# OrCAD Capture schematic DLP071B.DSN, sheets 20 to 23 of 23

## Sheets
20 PAGE04 - TEST INTERFACE CONNECT: size A3
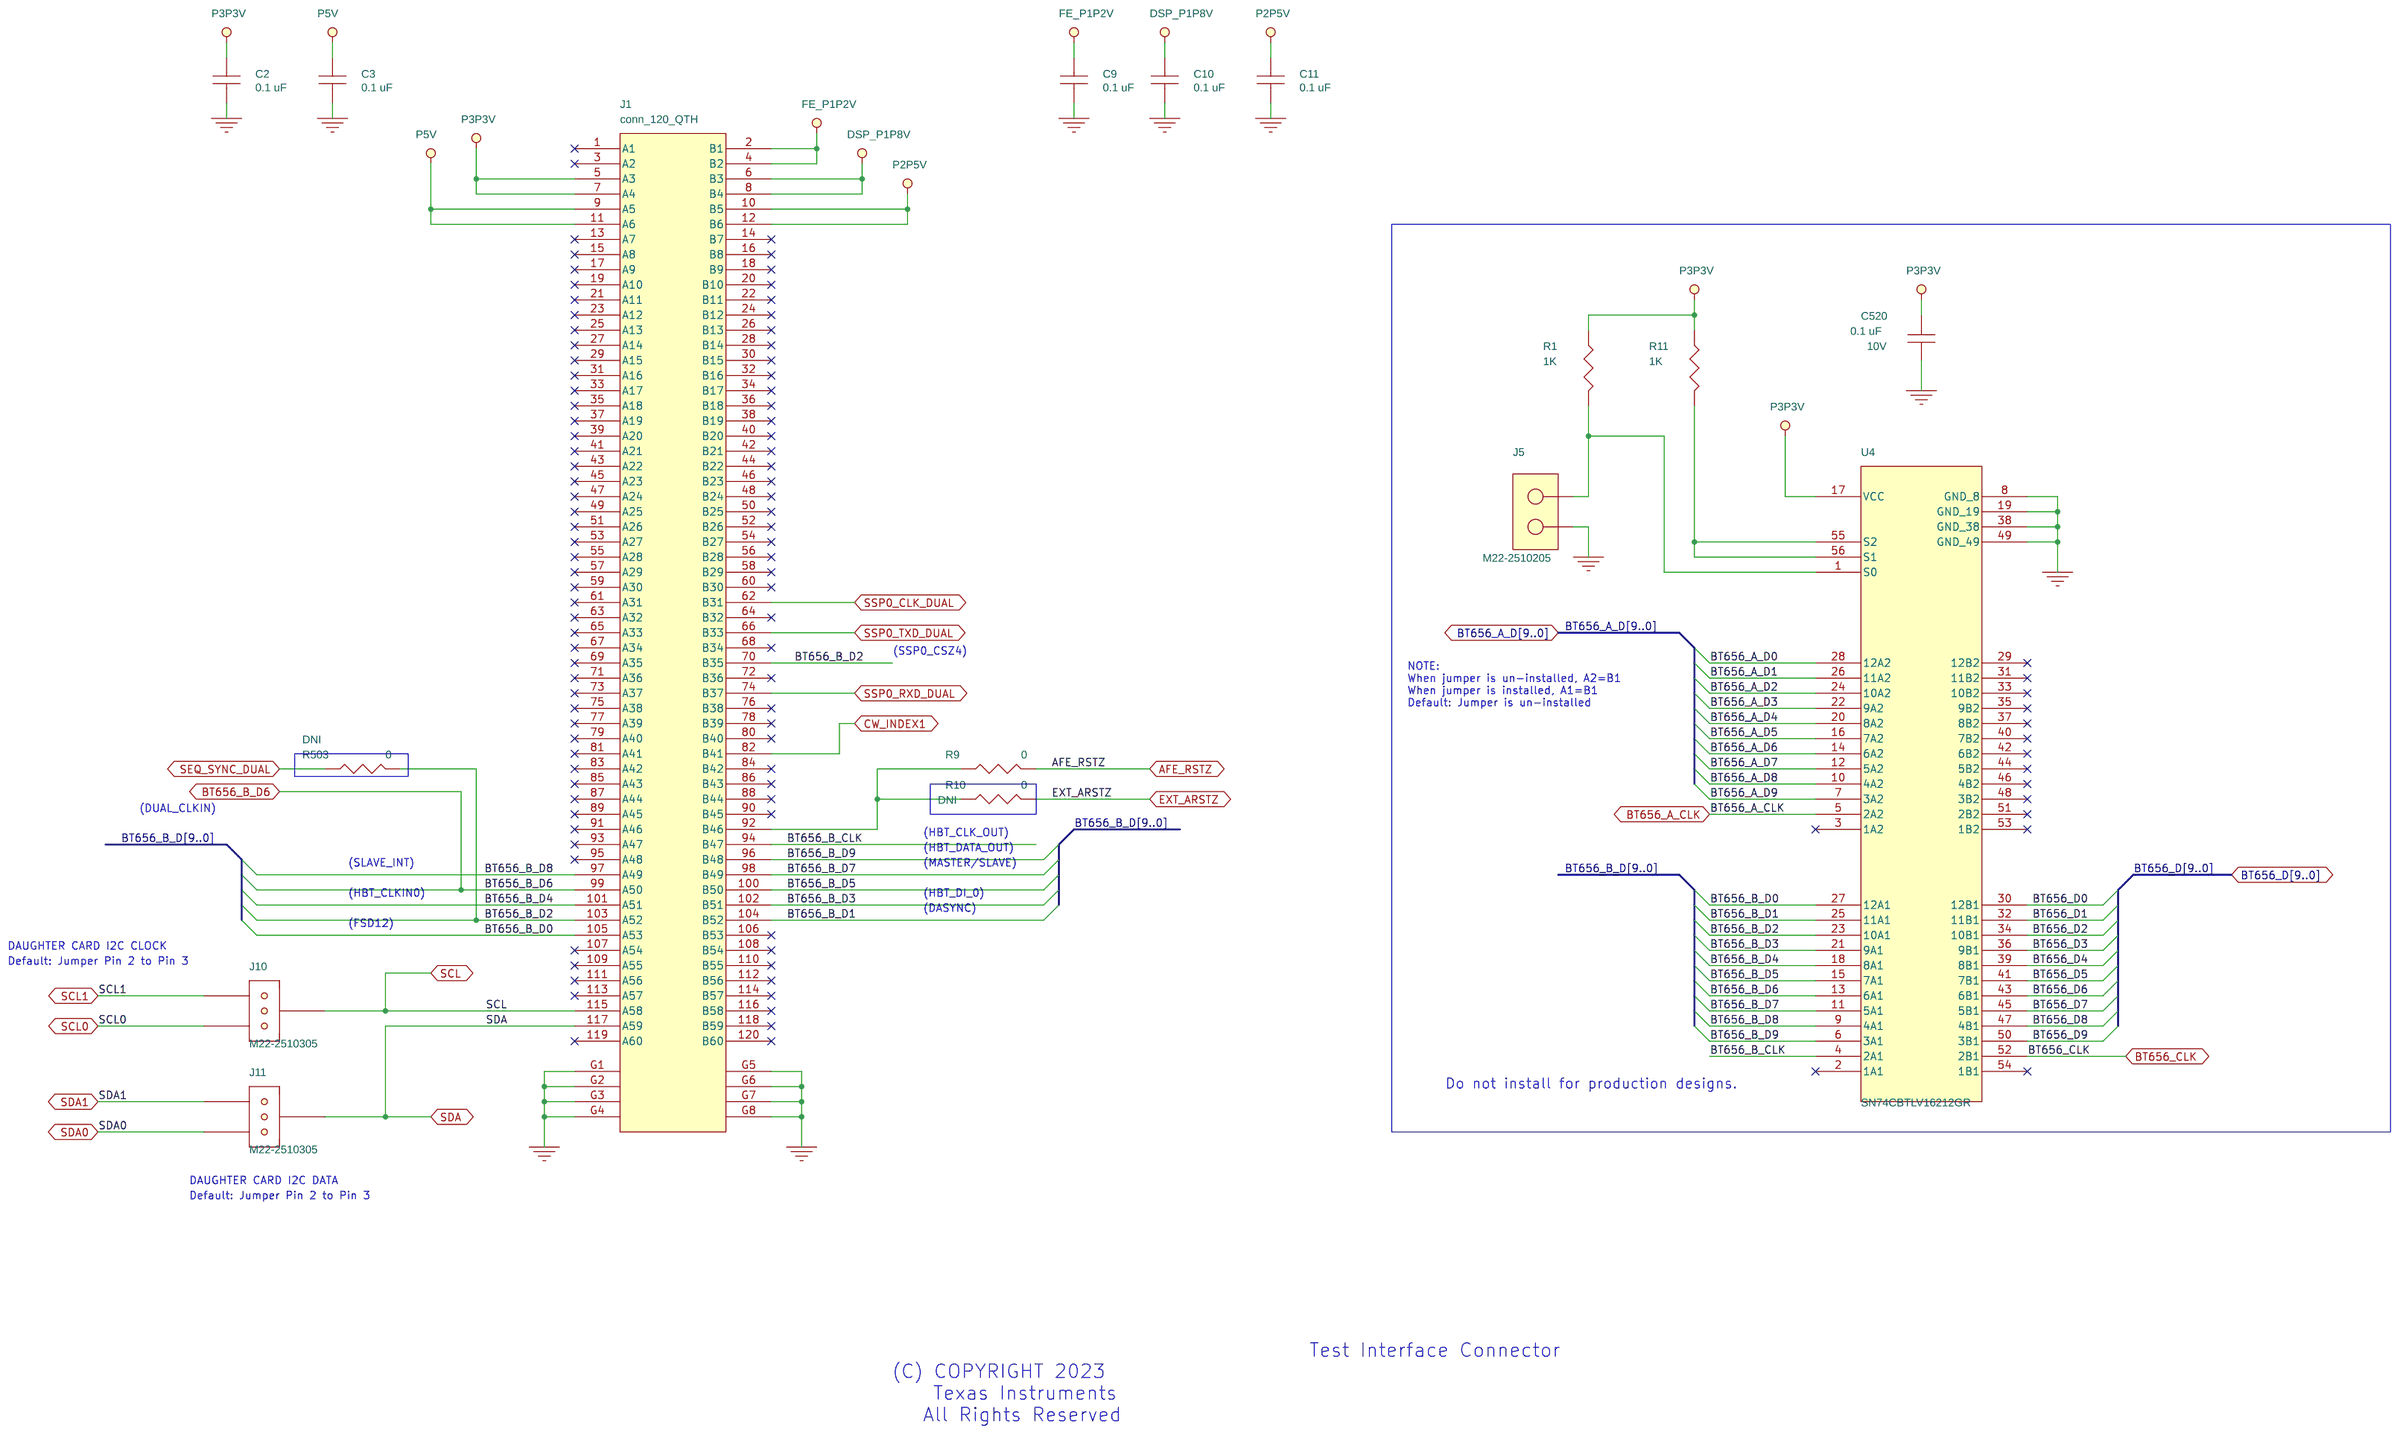
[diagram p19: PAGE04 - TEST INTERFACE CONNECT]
21 PAGE03 - AFE1000 INTERFACE: size A3
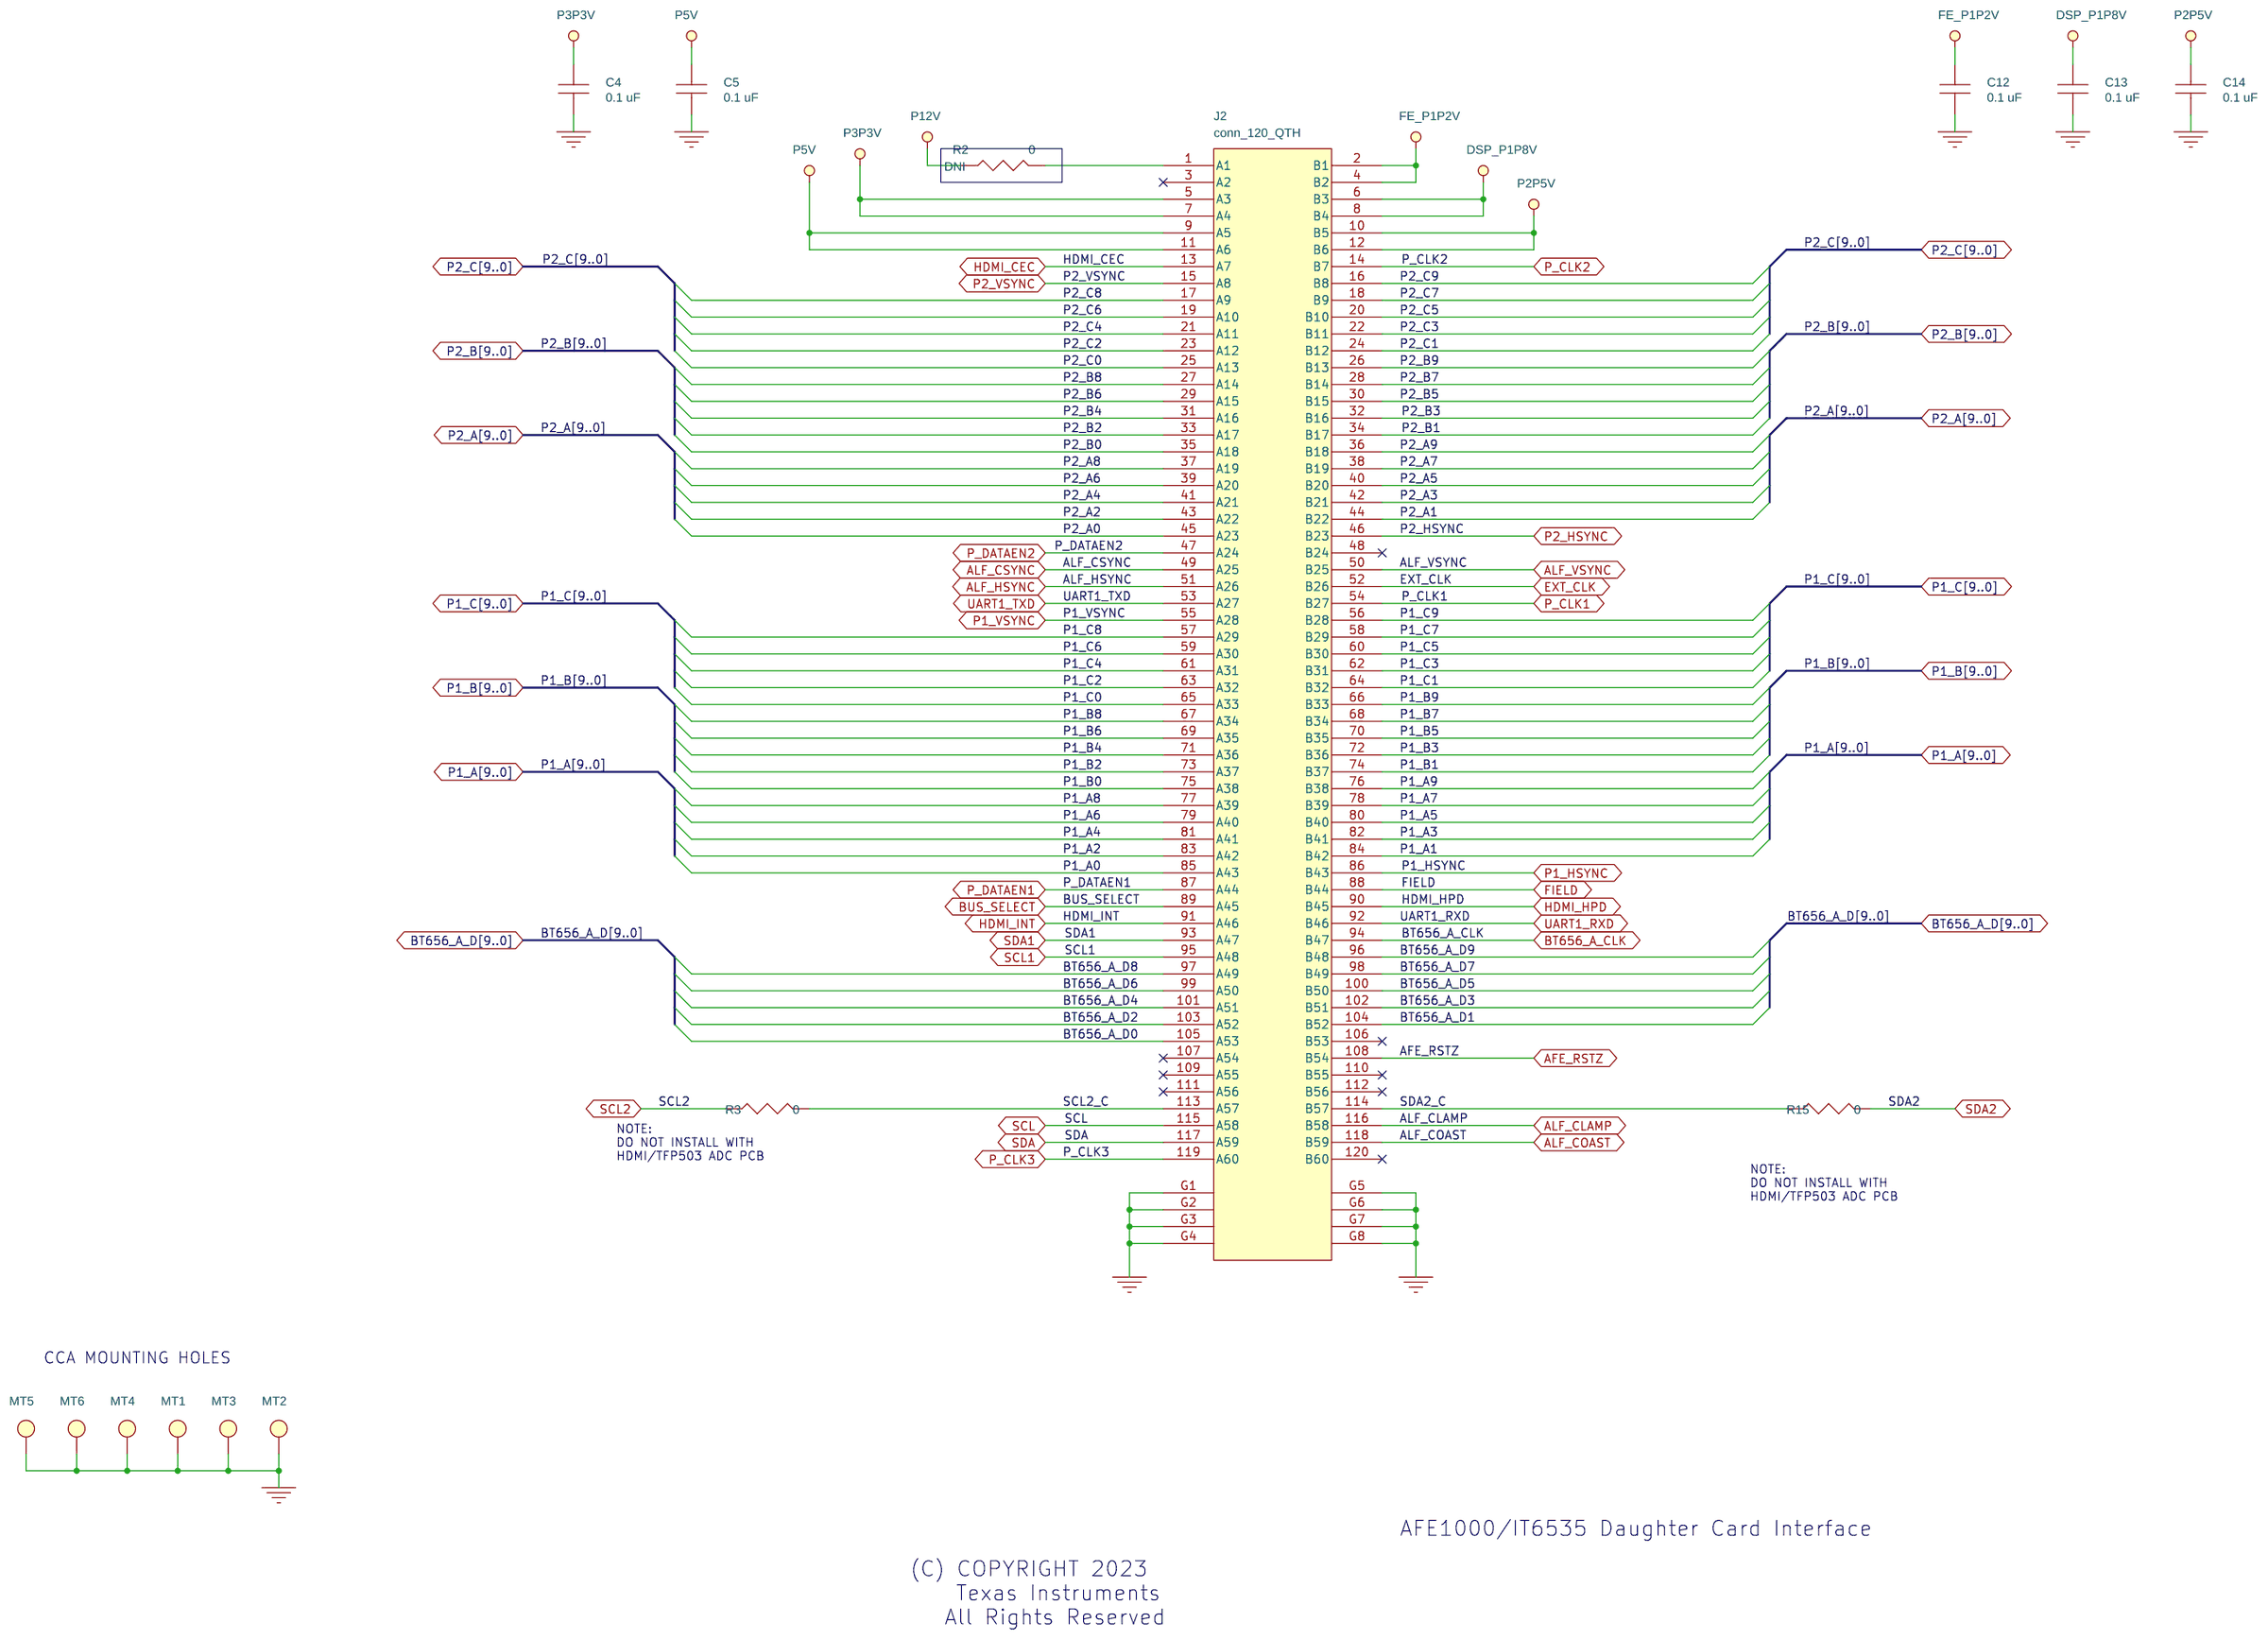
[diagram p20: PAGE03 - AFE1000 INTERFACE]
22 PAGE02 - BLOCK DIAGRAM
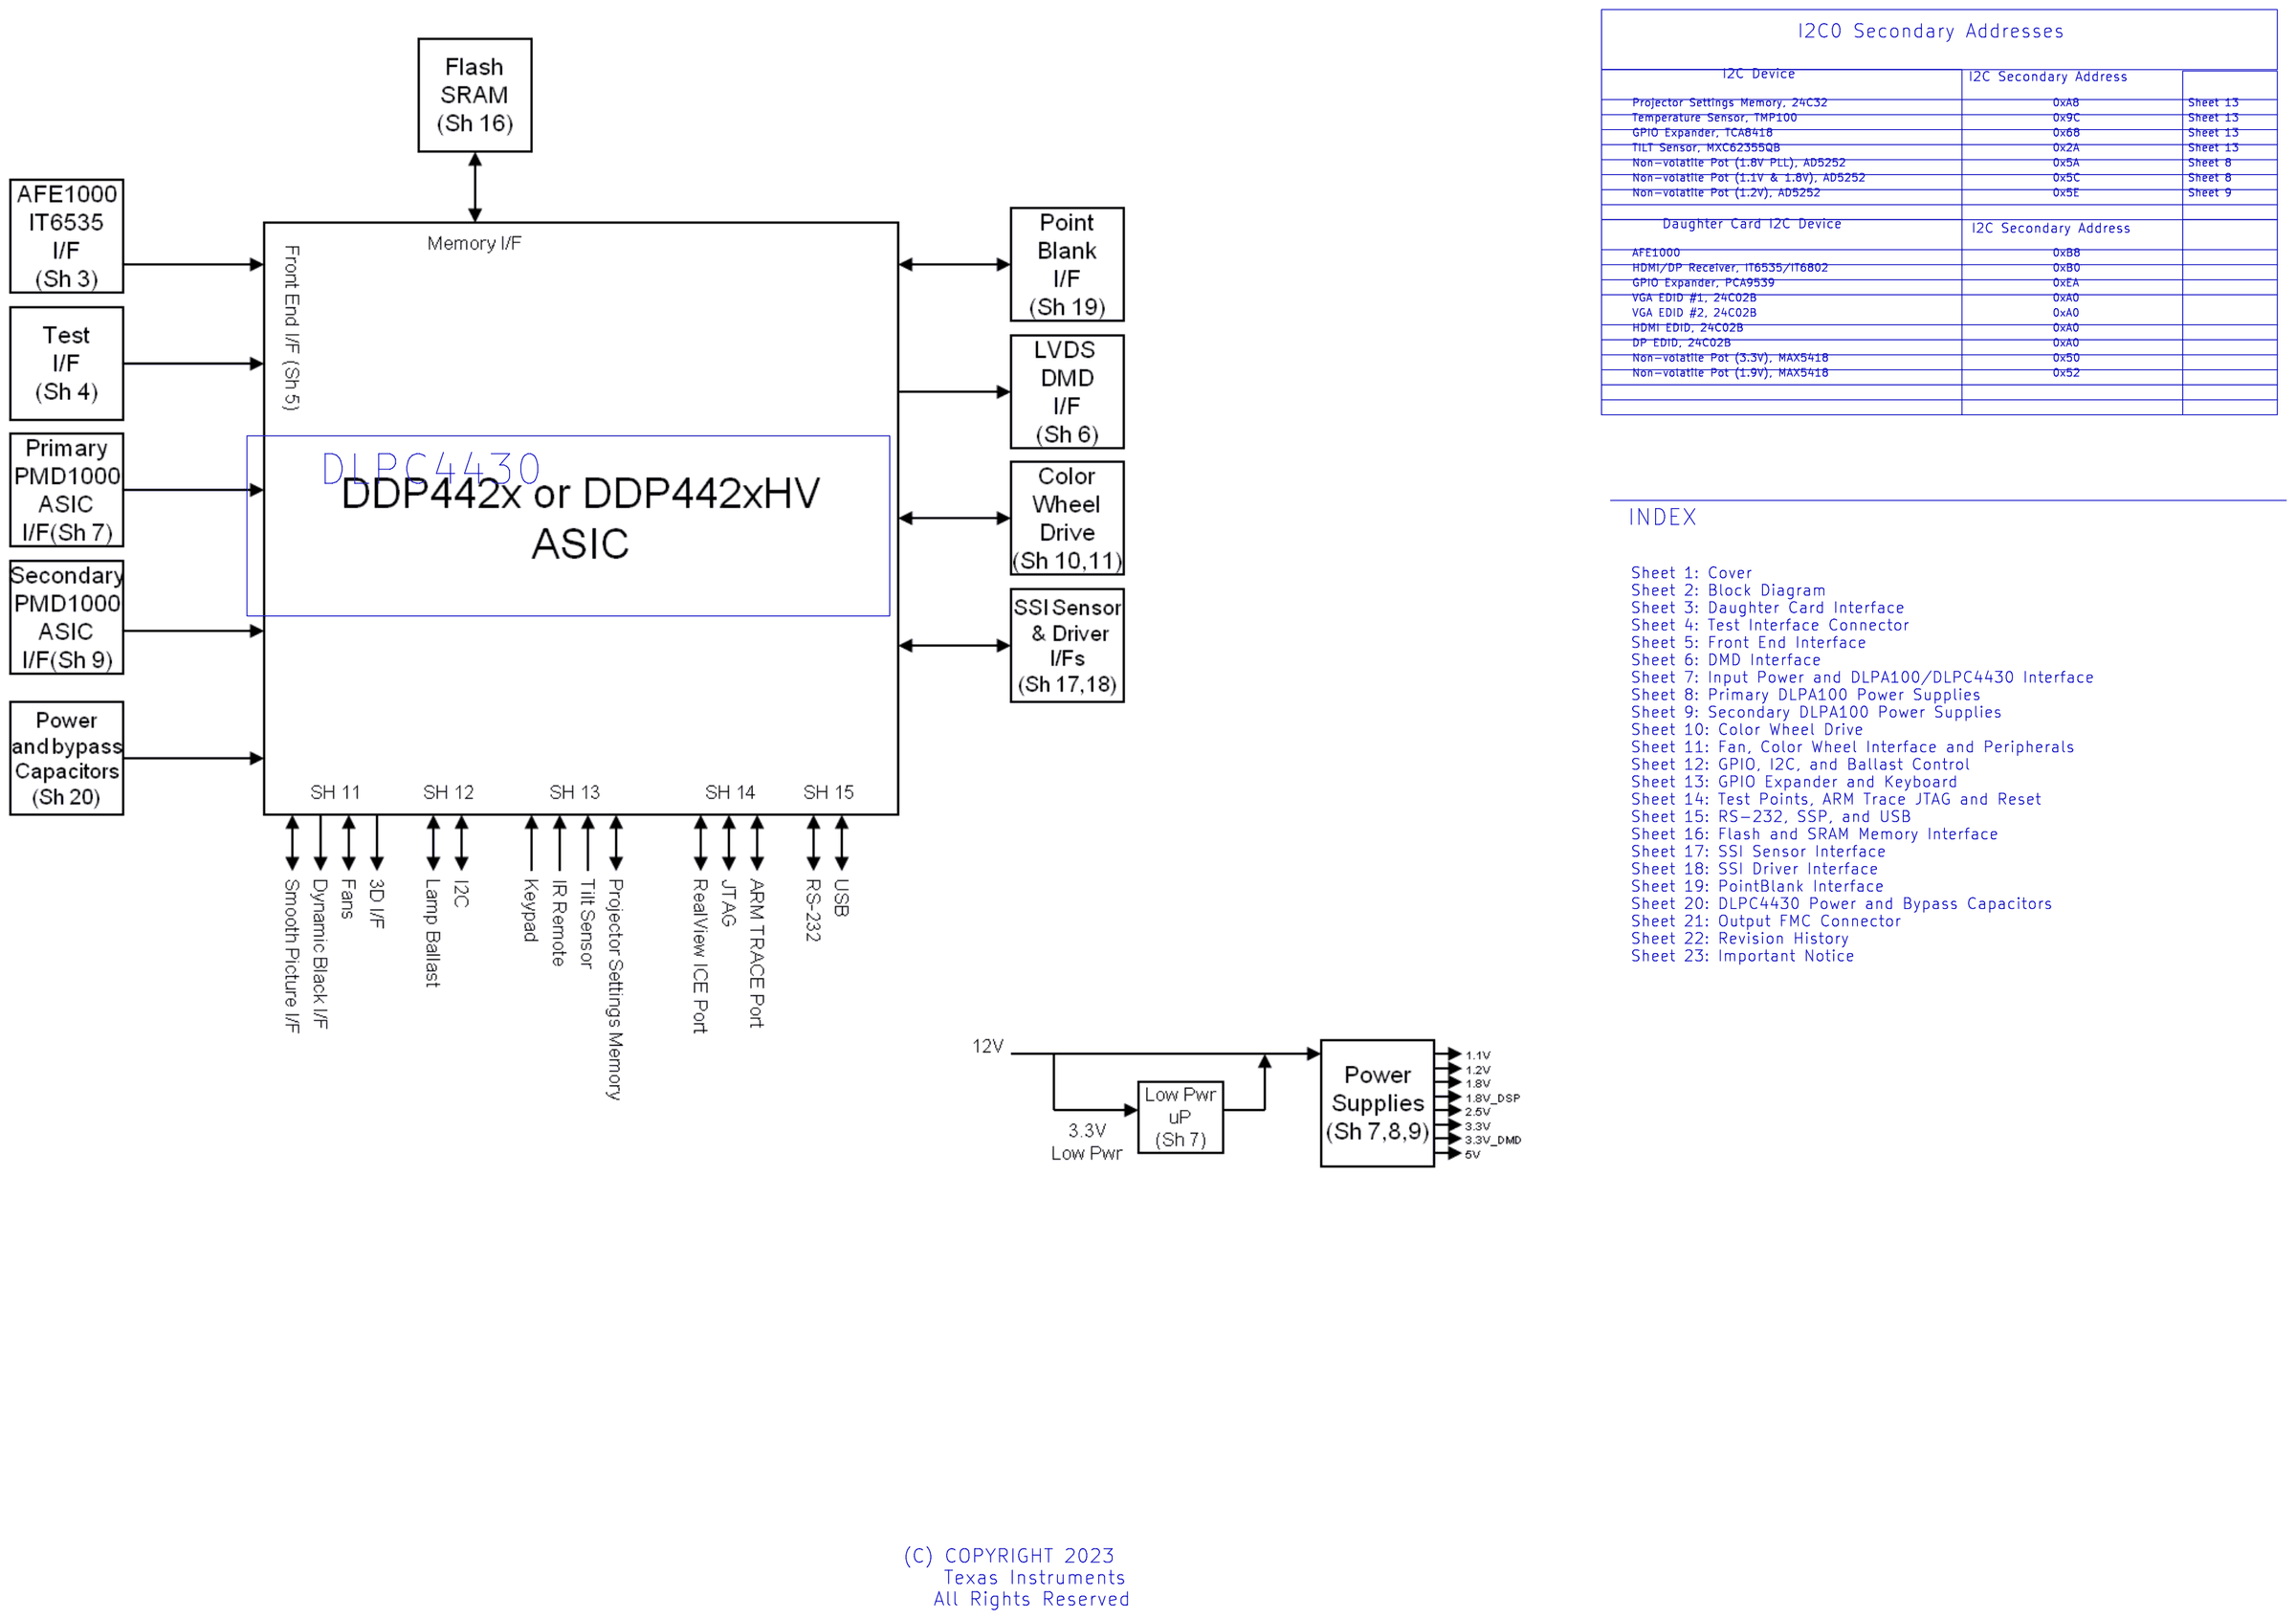
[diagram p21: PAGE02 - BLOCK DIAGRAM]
23 PAGE01 - TITLE: rev: D
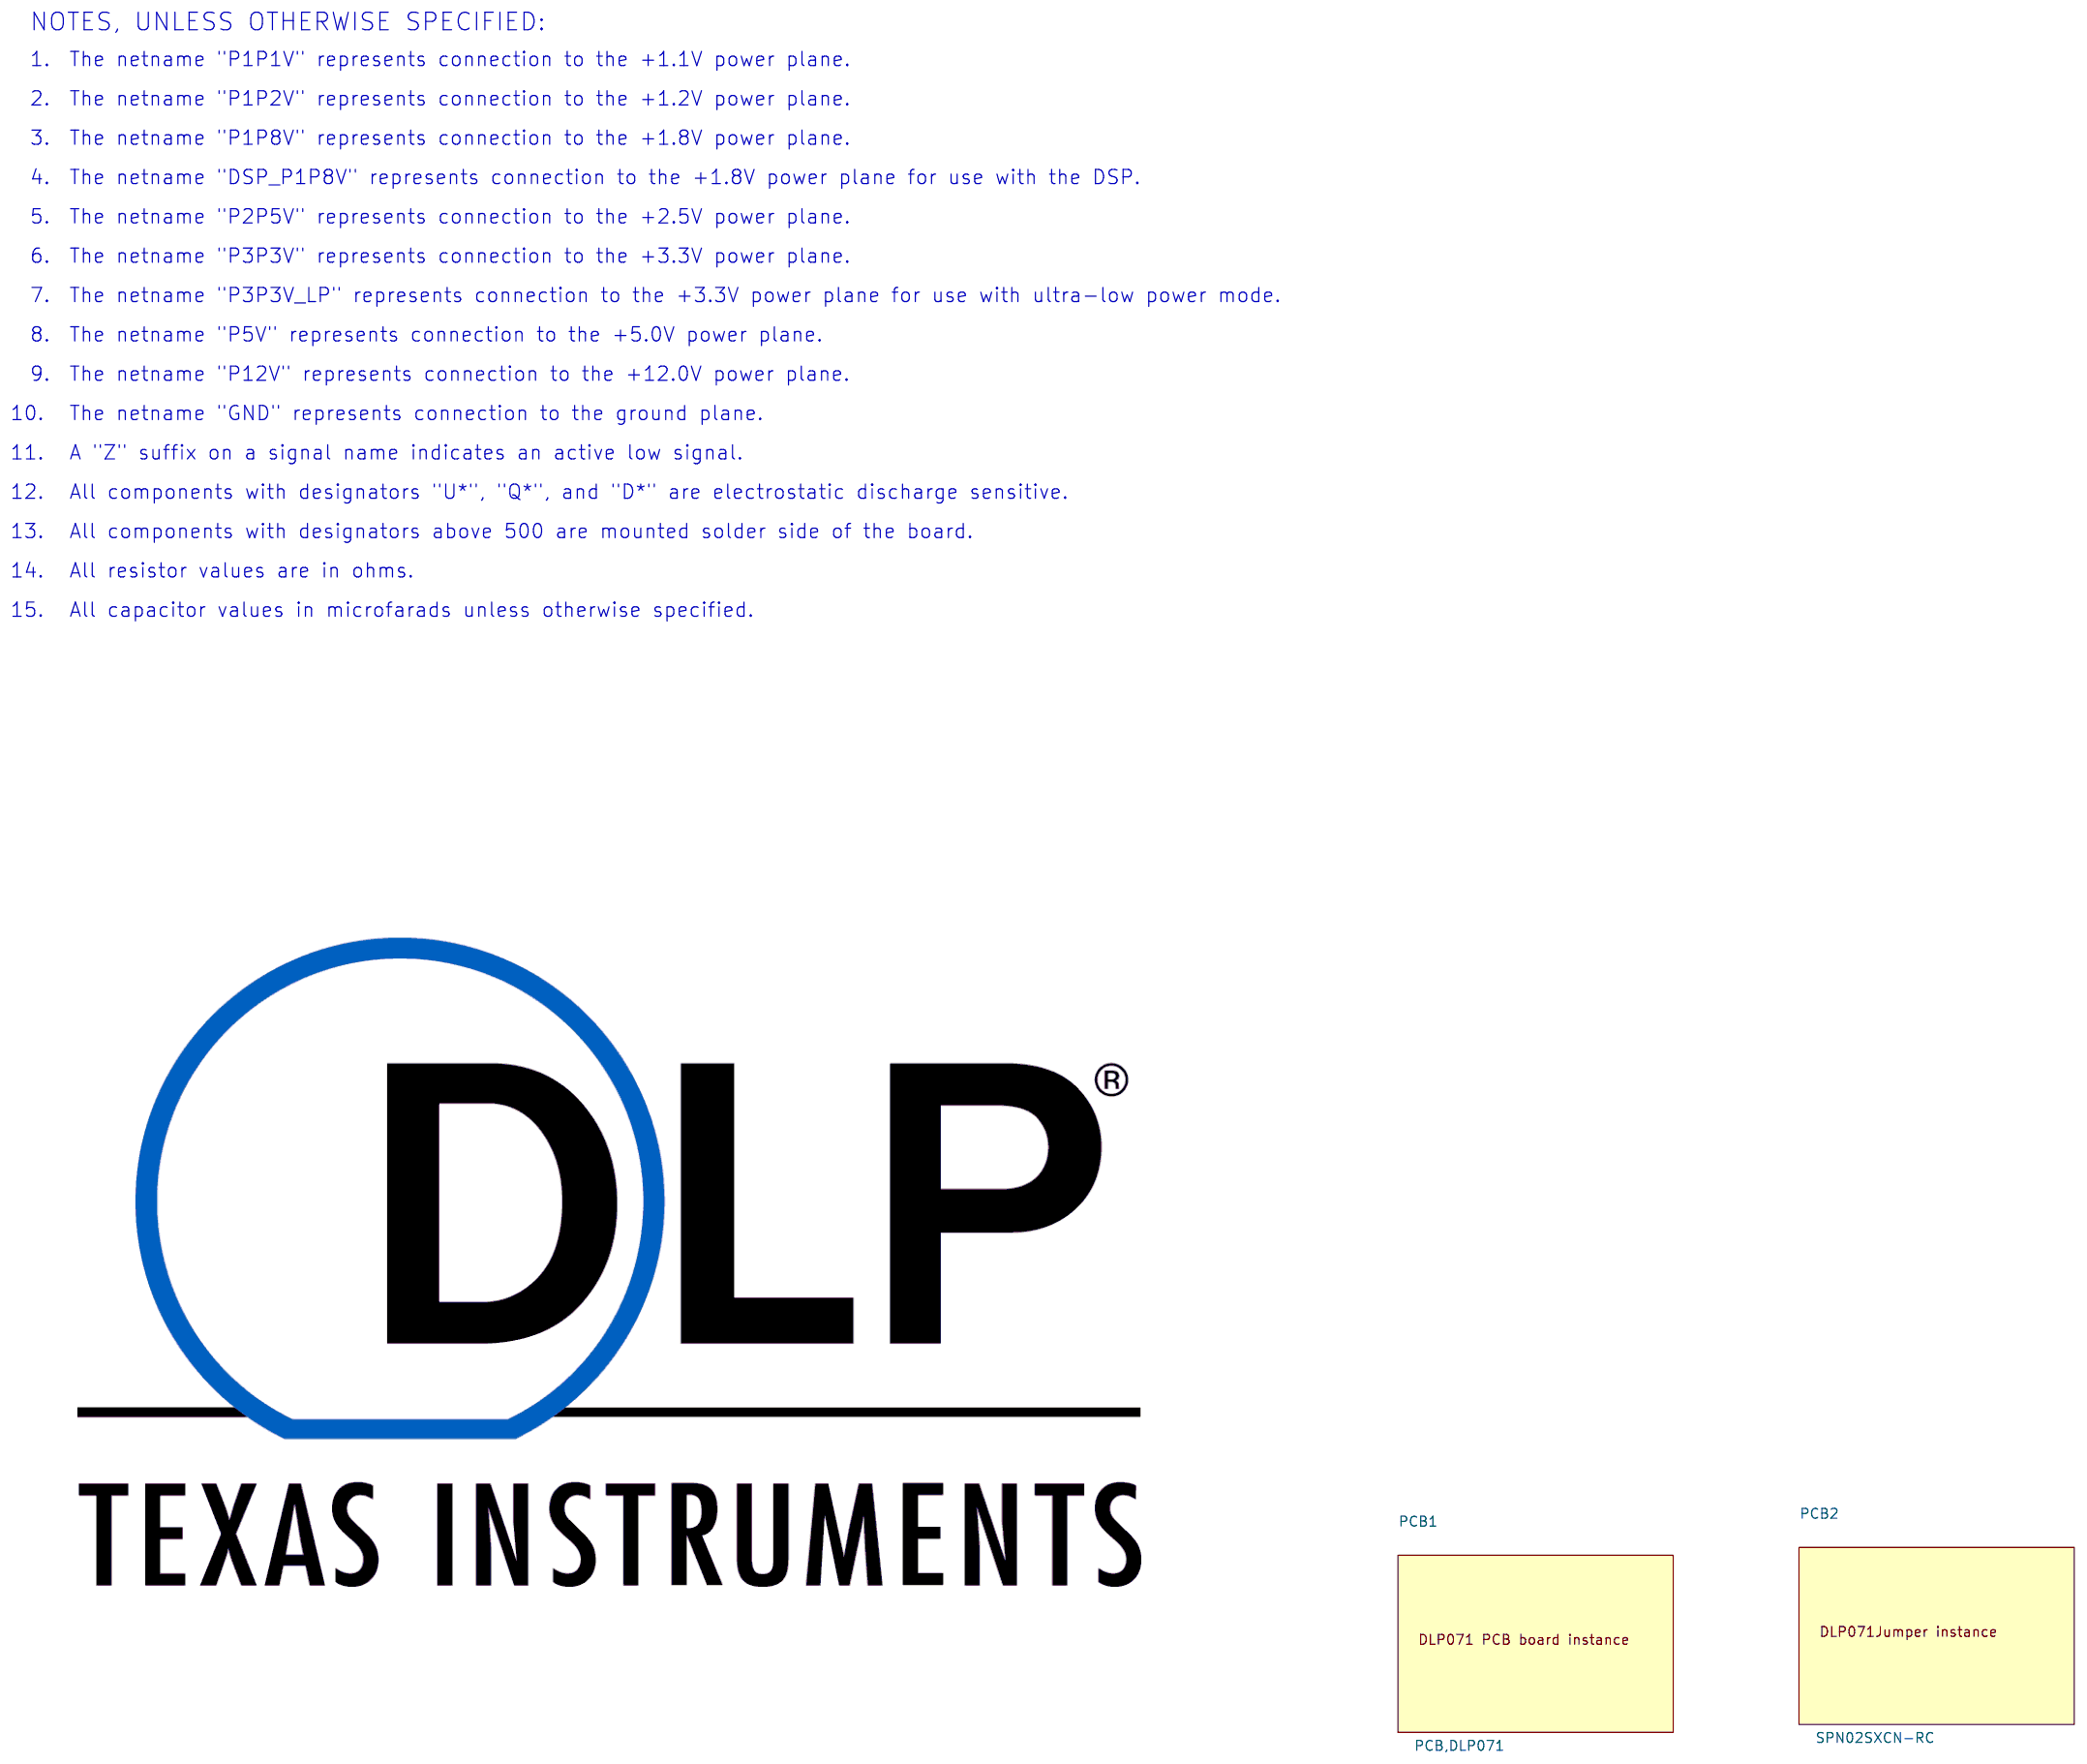
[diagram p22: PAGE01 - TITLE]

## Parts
sheet PAGE01 - TITLE
PCB1  PCB,DLP071
PCB2  SPN02SXCN-RC
sheet PAGE03 - AFE1000 INTERFACE
C4  0.1 uF  [CAP_0402]
C5  0.1 uF  [CAP_0402]
C12  0.1 uF  [CAP_0402]
C13  0.1 uF  [CAP_0402]
C14  0.1 uF  [CAP_0402]
J2  conn_120_QTH  [CN120_QTH_SAMTEC]
MT1  MOUNTING HOLE  [MH276-157GND-a]
MT2  MOUNTING HOLE  [MH276-157GND-a]
MT3  MOUNTING HOLE  [MH276-157GND-a]
MT4  MOUNTING HOLE  [MH276-157GND-a]
MT5  MOUNTING HOLE  [MH276-157GND-a]
MT6  MOUNTING HOLE  [MH276-157GND-a]
R2  0  [RES_0402]
R3  0  [RES_0402]
R15  0  [RES_0402]
sheet PAGE04 - TEST INTERFACE CONNECT
C2  0.1 uF  [CAP_0402]
C3  0.1 uF  [CAP_0402]
C9  0.1 uF  [CAP_0402]
C10  0.1 uF  [CAP_0402]
C11  0.1 uF  [CAP_0402]
C520  0.1 uF  [CAP_0402]
J1  conn_120_QTH  [CN120_QTH_SAMTEC]
J5  HDR_2  [HDR2_2MM]
J10  JUMPER-1x3  [HDR1X3-TMM1030X-X-S_SAM]
J11  JUMPER-1x3  [HDR1X3-TMM1030X-X-S_SAM]
R1  1K  [RES_0402]
R9  0  [RES_0402]
R10  0  [RES_0402]
R11  1K  [RES_0402]
R503  0  [RES_0402]
U4  74CBTLV16212  [SOIC56-DGG_TI]

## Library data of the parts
PCB1 = DLP027_0: DNI: DNI
PCB2 = DLP027_1: CONN JUMPER SHORTING 2MM GOLD; MFG: Sullins Conn.
C2-C5 C9-C14 C520 = CAP_NP: Capacitor; MFG: KEMET; Part Number: C0402C104K8RACTU; RATING: 10V; SOURCE: DIGI 399-3520-1-ND; TOLERANCE: 10%; Type: X7R
J1 J2 = conn_120_QTH: Connector, 120 pin; MFG: SAMTEC; Part Number: QTH-060-01-L-D-A; SOURCE: SAMTEC
MT1-MT6 = Testpoint_0: Mounting Hole; MFG: NA; Part Number: NA; SOURCE: NA
R2 R10 R503 = R: Resistor; DNI: DNI; ICA_MFR_NAME: PANASONIC; ICA_PARTNUM: $$1785048$$ERJ-3GSYJ102; MFG: PANASONIC; Part Number: ERJ-2GE0R00X; RATING: 1/10W; SOURCE: DIGI P0.0JCT-ND
R3 R9 R15 = R: Resistor; ICA_MFR_NAME: PANASONIC; ICA_PARTNUM: $$1785048$$ERJ-3GSYJ102; MFG: PANASONIC; Part Number: ERJ-2GE0R00X; RATING: 1/10W; SOURCE: DIGI P0.0JCT-ND
J5 = HDR_2: Jumper, 1x2; MFG: HARWIN; Part Number: M22-2510205; SOURCE: DIGI 952-1311-ND
J10 J11 = JUMPER-1x3: Jumper, 1x3; MFG: HARWIN; Part Number: M22-2510305; SOURCE: DIGI 952-1312-ND
R1 R11 = R: Resistor; ICA_MFR_NAME: PANASONIC; ICA_PARTNUM: $$1785048$$ERJ-3GSYJ102; MFG: PANASONIC; Part Number: ERJ-2GEJ102X; RATING: 1/10W; SOURCE: DIGI P1.0KJCT-ND; TOLERANCE: 5%
U4 = SN74CBTLV16212: IC, Bus-Exchange Switch; MFG: TI; Part Number: SN74CBTLV16212GR; SOURCE: DIGI 296-9102-1-ND

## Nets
GND: C2.2 C3.2 C4.2 C5.2 C9.2 C10.2 C11.2 C12.2 C13.2 C14.2 C520.1 J1.G1 J1.G2 J1.G3 J1.G4 J1.G5 J1.G6 J1.G7 J1.G8 J2.G1 J2.G2 J2.G3 J2.G4 J2.G5 J2.G6 J2.G7 J2.G8 J5.2 MT1.1 MT2.1 MT3.1 MT4.1 MT5.1 MT6.1 U4.8(GND) U4.19(GND) U4.38(GND) U4.49(GND) ; also on sheet 1 4 5 6 7 8 9 10 11 12 13 14 15 16 17 18
P5V: C3.1 C5.1 J1.9(A5) J1.11(A6) J2.9(A5) J2.11(A6) ; also on sheet 5 7 12 13 16
P12V: R2.1 ; also on sheet 1 6 13 14 15 16 17
AFE_RSTZ: J2.108(B54) R9.1 ; also on sheet 19
ALF_CLAMP: J2.116(B58) ; also on sheet 12
ALF_COAST: J2.118(B59) ; also on sheet 12
ALF_CSYNC: J2.49(A25) ; also on sheet 19
ALF_HSYNC: J2.51(A26) ; also on sheet 19
ALF_VSYNC: J2.50(B25) ; also on sheet 19
BT656_A_CLK: J2.94(B47) U4.5(2A2)
BT656_A_D0: J2.105(A53) U4.28(12A2)
BT656_A_D1: J2.104(B52) U4.26(11A2)
BT656_A_D2: J2.103(A52) U4.24(10A2)
BT656_A_D3: J2.102(B51) U4.22(9A2)
BT656_A_D4: J2.101(A51) U4.20(8A2)
BT656_A_D5: J2.100(B50) U4.16(7A2)
BT656_A_D6: J2.99(A50) U4.14(6A2)
BT656_A_D7: J2.98(B49) U4.12(5A2)
BT656_A_D8: J2.97(A49) U4.10(4A2)
BT656_A_D9: J2.96(B48) U4.7(3A2)
BT656_B_CLK: J1.94(B47) U4.4(2A1)
BT656_B_D0: J1.105(A53) U4.27(12A1)
BT656_B_D1: J1.104(B52) U4.25(11A1)
BT656_B_D2: J1.70(B35) J1.103(A52) R503.1 U4.23(10A1)
BT656_B_D3: J1.102(B51) U4.21(9A1)
BT656_B_D4: J1.101(A51) U4.18(8A1)
BT656_B_D5: J1.100(B50) U4.15(7A1)
BT656_B_D6: J1.99(A50) U4.13(6A1) ; also on sheet 17
BT656_B_D7: J1.98(B49) U4.11(5A1)
BT656_B_D8: J1.97(A49) U4.9(4A1)
BT656_B_D9: J1.96(B48) U4.6(3A1)
BT656_CLK: U4.52(2B1) ; also on sheet 12
BT656_D0: U4.30(12B1) ; also on sheet 12
BT656_D1: U4.32(11B1) ; also on sheet 12
BT656_D2: U4.34(10B1) ; also on sheet 12
BT656_D3: U4.36(9B1) ; also on sheet 12
BT656_D4: U4.39(8B1) ; also on sheet 12
BT656_D5: U4.41(7B1) ; also on sheet 12
BT656_D6: U4.43(6B1) ; also on sheet 12
BT656_D7: U4.45(5B1) ; also on sheet 12
BT656_D8: U4.47(4B1) ; also on sheet 12
BT656_D9: U4.50(3B1) ; also on sheet 12
BUS_SELECT: J2.89(A45) ; also on sheet 11
CW_INDEX1: J1.82(B41) ; also on sheet 13 17
DSP_P1P8V: C10.1 C13.1 J1.6(B3) J1.8(B4) J2.6(B3) J2.8(B4) ; also on sheet 15
EXT_ARSTZ: R10.1 ; also on sheet 1 13 17
EXT_CLK: J2.52(B26) ; also on sheet 19
FE_P1P2V: C9.1 C12.1 J1.2(B1) J1.4(B2) J2.2(B1) J2.4(B2) ; also on sheet 15
FIELD: J2.88(B44) ; also on sheet 12 19
HDMI_CEC: J2.13(A7) ; also on sheet 19
HDMI_HPD: J2.90(B45) ; also on sheet 11
HDMI_INT: J2.91(A46) ; also on sheet 19
P1_A0: J2.85(A43) ; also on sheet 19
P1_A1: J2.84(B42) ; also on sheet 19
P1_A2: J2.83(A42) ; also on sheet 19
P1_A3: J2.82(B41) ; also on sheet 19
P1_A4: J2.81(A41) ; also on sheet 19
P1_A5: J2.80(B40) ; also on sheet 19
P1_A6: J2.79(A40) ; also on sheet 19
P1_A7: J2.78(B39) ; also on sheet 19
P1_A8: J2.77(A39) ; also on sheet 19
P1_A9: J2.76(B38) ; also on sheet 19
P1_B0: J2.75(A38) ; also on sheet 19
P1_B1: J2.74(B37) ; also on sheet 19
P1_B2: J2.73(A37) ; also on sheet 19
P1_B3: J2.72(B36) ; also on sheet 19
P1_B4: J2.71(A36) ; also on sheet 19
P1_B5: J2.70(B35) ; also on sheet 19
P1_B6: J2.69(A35) ; also on sheet 19
P1_B7: J2.68(B34) ; also on sheet 19
P1_B8: J2.67(A34) ; also on sheet 19
P1_B9: J2.66(B33) ; also on sheet 19
P1_C0: J2.65(A33) ; also on sheet 19
P1_C1: J2.64(B32) ; also on sheet 19
P1_C2: J2.63(A32) ; also on sheet 19
P1_C3: J2.62(B31) ; also on sheet 19
P1_C4: J2.61(A31) ; also on sheet 19
P1_C5: J2.60(B30) ; also on sheet 19
P1_C6: J2.59(A30) ; also on sheet 19
P1_C7: J2.58(B29) ; also on sheet 19
P1_C8: J2.57(A29) ; also on sheet 19
P1_C9: J2.56(B28) ; also on sheet 19
P1_HSYNC: J2.86(B43) ; also on sheet 19
P1_VSYNC: J2.55(A28) ; also on sheet 19
P2_A0: J2.45(A23) ; also on sheet 19
P2_A1: J2.44(B22) ; also on sheet 19
P2_A2: J2.43(A22) ; also on sheet 19
P2_A3: J2.42(B21) ; also on sheet 19
P2_A4: J2.41(A21) ; also on sheet 19
P2_A5: J2.40(B20) ; also on sheet 19
P2_A6: J2.39(A20) ; also on sheet 19
P2_A7: J2.38(B19) ; also on sheet 19
P2_A8: J2.37(A19) ; also on sheet 19
P2_A9: J2.36(B18) ; also on sheet 19
P2_B0: J2.35(A18) ; also on sheet 19
P2_B1: J2.34(B17) ; also on sheet 19
P2_B2: J2.33(A17) ; also on sheet 19
P2_B3: J2.32(B16) ; also on sheet 19
P2_B4: J2.31(A16) ; also on sheet 19
P2_B5: J2.30(B15) ; also on sheet 19
P2_B6: J2.29(A15) ; also on sheet 19
P2_B7: J2.28(B14) ; also on sheet 19
P2_B8: J2.27(A14) ; also on sheet 19
P2_B9: J2.26(B13) ; also on sheet 19
P2_C0: J2.25(A13) ; also on sheet 19
P2_C1: J2.24(B12) ; also on sheet 19
P2_C2: J2.23(A12) ; also on sheet 19
P2_C3: J2.22(B11) ; also on sheet 19
P2_C4: J2.21(A11) ; also on sheet 19
P2_C5: J2.20(B10) ; also on sheet 19
P2_C6: J2.19(A10) ; also on sheet 19
P2_C7: J2.18(B9) ; also on sheet 19
P2_C8: J2.17(A9) ; also on sheet 19
P2_C9: J2.16(B8) ; also on sheet 19
P2_HSYNC: J2.46(B23) ; also on sheet 19
P2_VSYNC: J2.15(A8) ; also on sheet 19
P2P5V: C11.1 C14.1 J1.10(B5) J1.12(B6) J2.10(B5) J2.12(B6) ; also on sheet 16
P3P3V: C2.1 C4.1 C520.2 J1.5(A3) J1.7(A4) J2.5(A3) J2.7(A4) R1.1 R11.1 U4.17(VCC) ; also on sheet 4 5 6 7 8 9 10 11 12 13 14 15 16 17 18
P_CLK1: J2.54(B27) ; also on sheet 19
P_CLK2: J2.14(B7) ; also on sheet 19
P_CLK3: J2.119(A60) ; also on sheet 19
P_DATAEN1: J2.87(A44) ; also on sheet 19
P_DATAEN2: J2.47(A24) ; also on sheet 19
SCL: J1.115(A58) J2.115(A58) J10.2
SCL0: J10.3 ; also on sheet 11 12 16
SCL1: J2.95(A48) J10.1 ; also on sheet 12
SCL2: R3.1 ; also on sheet 12
SCL2_C: J2.113(A57) R3.2
SDA: J1.117(A59) J2.117(A59) J11.2
SDA0: J11.3 ; also on sheet 11 12 16
SDA1: J2.93(A47) J11.1 ; also on sheet 12
SDA2: R15.1 ; also on sheet 12
SDA2_C: J2.114(B57) R15.2
SEQ_SYNC_DUAL: R503.2 ; also on sheet 10
SSP0_CLK_DUAL: J1.62(B31) ; also on sheet 9
SSP0_RXD_DUAL: J1.74(B37) ; also on sheet 9
SSP0_TXD_DUAL: J1.66(B33) ; also on sheet 9
UART1_RXD: J2.92(B46) ; also on sheet 9 12
UART1_TXD: J2.53(A27) ; also on sheet 9 12
N16773791: J2.1(A1) R2.2
N16781966: J1.92(B46) R9.2 R10.2
N16869658: J5.1 R1.2 U4.1(S0)
N16869662: R11.2 U4.55(S2) U4.56(S1)

Not connected (* = marked no-connect by the designer): J1 1(A1)* 3(A2)* 13(A7)* 14(B7)* 15(A8)* 16(B8)* 17(A9)* 18(B9)* 19(A10)* 20(B10)* 21(A11)* 22(B11)* 23(A12)* 24(B12)* 25(A13)* 26(B13)* 27(A14)* 28(B14)* 29(A15)* 30(B15)* 31(A16)* 32(B16)* 33(A17)* 34(B17)* 35(A18)* 36(B18)* 37(A19)* 38(B19)* 39(A20)* 40(B20)* 41(A21)* 42(B21)* 43(A22)* 44(B22)* 45(A23)* 46(B23)* 47(A24)* 48(B24)* 49(A25)* 50(B25)* 51(A26)* 52(B26)* 53(A27)* 54(B27)* 55(A28)* 56(B28)* 57(A29)* 58(B29)* 59(A30)* 60(B30)* 61(A31)* 63(A32)* 64(B32)* 65(A33)* 67(A34)* 68(B34)* 69(A35)* 71(A36)* 72(B36)* 73(A37)* 75(A38)* 76(B38)* 77(A39)* 78(B39)* 79(A40)* 80(B40)* 81(A41)* 83(A42)* 84(B42)* 85(A43)* 86(B43)* 87(A44)* 88(B44)* 89(A45)* 90(B45)* 91(A46)* 93(A47)* 95(A48)* 106(B53)* 107(A54)* 108(B54)* 109(A55)* 110(B55)* 111(A56)* 112(B56)* 113(A57)* 114(B57)* 116(B58)* 118(B59)* 119(A60)* 120(B60)*; J2 3(A2)* 48(B24)* 106(B53)* 107(A54)* 109(A55)* 110(B55)* 111(A56)* 112(B56)* 120(B60)*; U4 2(1A1)* 3(1A2)* 29(12B2)* 31(11B2)* 33(10B2)* 35(9B2)* 37(8B2)* 40(7B2)* 42(6B2)* 44(5B2)* 46(4B2)* 48(3B2)* 51(2B2)* 53(1B2)* 54(1B1)*

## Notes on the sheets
sheet 20
- (SSP0_CSZ4)
- NOTE:
  When jumper is un-installed, A2=B1
  When jumper is installed, A1=B1
  Default: Jumper is un-installed
- (DUAL_CLKIN)
- (HBT_CLK_OUT)
- (HBT_DATA_OUT)
- (SLAVE_INT)
- (MASTER/SLAVE)
- (HBT_CLKIN0)
- (HBT_DI_0)
- (DASYNC)
- (FSD12)
- DAUGHTER CARD I2C CLOCK
- Default: Jumper Pin 2 to Pin 3
- Do not install for production designs.
- DAUGHTER CARD I2C DATA
- Default: Jumper Pin 2 to Pin 3
- Test Interface Connector
- (C) COPYRIGHT 2023
         Texas Instruments
        All Rights Reserved
sheet 21
- NOTE:
  DO NOT INSTALL WITH
  HDMI/TFP503 ADC PCB
- NOTE:
  DO NOT INSTALL WITH
  HDMI/TFP503 ADC PCB
- CCA MOUNTING HOLES
- AFE1000/IT6535 Daughter Card Interface
- (C) COPYRIGHT 2023
         Texas Instruments
        All Rights Reserved
sheet 22
- I2C0 Secondary Addresses
- I2C Device
- I2C Secondary Address
- Projector Settings Memory, 24C32
- 0xA8
- Sheet 13
- Temperature Sensor, TMP100
- 0x9C
- Sheet 13
- GPIO Expander, TCA8418
- 0x68
- Sheet 13
- TILT Sensor, MXC62355QB
- 0x2A
- Sheet 13
- Non-volatile Pot (1.8V PLL), AD5252
- 0x5A
- Sheet 8
- Non-volatile Pot (1.1V & 1.8V), AD5252
- Non-volatile Pot (1.2V), AD5252
- 0x5C
- 0x5E
- Sheet 8
- Sheet 9
- Daughter Card I2C Device
- I2C Secondary Address
- AFE1000
- 0xB8
- HDMI/DP Receiver, IT6535/IT6802
- 0xB0
- GPIO Expander, PCA9539
- VGA EDID #1, 24C02B
- 0xA0
- 0xEA
- VGA EDID #2, 24C02B
- 0xA0
- HDMI EDID, 24C02B
- 0xA0
- DP EDID, 24C02B
- 0xA0
- Non-volatile Pot (3.3V), MAX5418
- 0x50
- Non-volatile Pot (1.9V), MAX5418
- 0x52
- DLPC4430
- INDEX
- Sheet 1: Cover
  Sheet 2: Block Diagram
  Sheet 3: Daughter Card Interface
  Sheet 4: Test Interface Connector
  Sheet 5: Front End Interface
  Sheet 6: DMD Interface
  Sheet 7: Input Power and DLPA100/DLPC4430 Interface
  Sheet 8: Primary DLPA100 Power Supplies
  Sheet 9: Secondary DLPA100 Power Supplies
  Sheet 10: Color Wheel Drive
  Sheet 11: Fan, Color Wheel Interface and Peripherals
  Sheet 12: GPIO, I2C, and Ballast Control
  Sheet 13: GPIO Expander and Keyboard
  Sheet 14: Test Points, ARM Trace JTAG and Reset
  Sheet 15: RS-232, SSP, and USB
  Sheet 16: Flash and SRAM Memory Interface
  Sheet 17: SSI Sensor Interface
  Sheet 18: SSI Driver Interface
  Sheet 19: PointBlank Interface
  Sheet 20: DLPC4430 Power and Bypass Capacitors
  Sheet 21: Output FMC Connector
  Sheet 22: Revision History
  Sheet 23: Important Notice
- (C) COPYRIGHT 2023
         Texas Instruments
        All Rights Reserved
sheet 23
- NOTES, UNLESS OTHERWISE SPECIFIED:
- 1.
- The netname "P1P1V" represents connection to the +1.1V power plane.
- 2.
- The netname "P1P2V" represents connection to the +1.2V power plane.
- 3.
- The netname "P1P8V" represents connection to the +1.8V power plane.
- 4.
- The netname "DSP_P1P8V" represents connection to the +1.8V power plane for use with the DSP.
- 5.
- The netname "P2P5V" represents connection to the +2.5V power plane.
- 6.
- The netname "P3P3V" represents connection to the +3.3V power plane.
- 7.
- The netname "P3P3V_LP" represents connection to the +3.3V power plane for use with ultra-low power mode.
- 8.
- The netname "P5V" represents connection to the +5.0V power plane.
- 9.
- The netname "P12V" represents connection to the +12.0V power plane.
- 10.
- The netname "GND" represents connection to the ground plane.
- 11.
- A "Z" suffix on a signal name indicates an active low signal.
- 12.
- All components with designators "U*", "Q*", and "D*" are electrostatic discharge sensitive.
- 13.
- All components with designators above 500 are mounted solder side of the board.
- 14.
- All resistor values are in ohms.
- 15.
- All capacitor values in microfarads unless otherwise specified.
